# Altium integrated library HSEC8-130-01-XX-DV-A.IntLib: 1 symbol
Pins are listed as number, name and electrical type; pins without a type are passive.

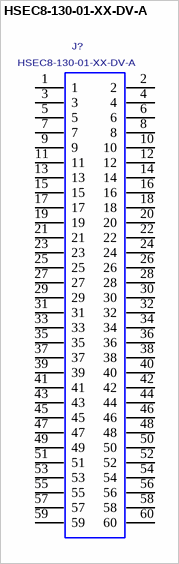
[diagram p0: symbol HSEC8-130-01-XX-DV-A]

## HSEC8-130-01-XX-DV-A
designator J?
0.8MM PITCH HIGH SPEED ASSEMBLY, 60PINS; MANUFACTURER: SAMTEC
footprint HSEC8-130-01-XX-DV-A
pins: 1, 2, 3, 4, 5, 6, 7, 8, 9, 10, 11, 12, 13, 14, 15, 16, 17, 18, 19, 20, 21, 22, 23, 24, 25, 26, 27, 28, 29, 30, 31, 32, 33, 34, 35, 36, 37, 38, 39, 40, 41, 42, 43, 44, 45, 46, 47, 48, 49, 50, 51, 52, 53, 54, 55, 56, 57, 58, 59, 60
